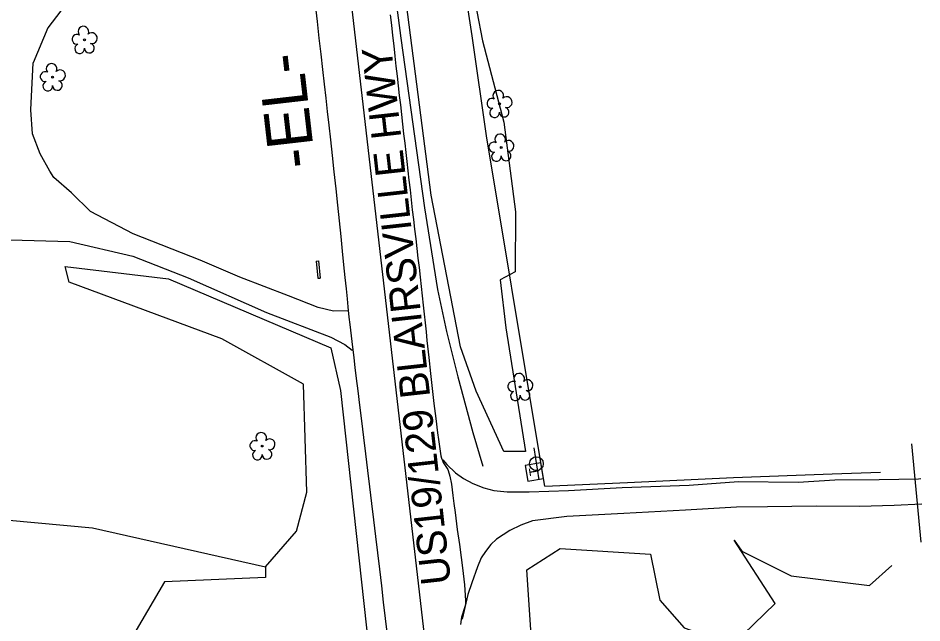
# Model space of a CAD drawing. Extents: x 476627 to 479509, y 495837 to 499842.
# Drawn here: x 478091.3 to 478407.5, y 496570.2 to 496781.9 of the extents above; entities that cross this region are included whole.
import ezdxf

# ---------------------------------------------------------------- set-up
doc = ezdxf.new("R2010")
doc.units = 0
for name, color, linetype in [('Exist Guardrail', 7, 'Continuous'), ('Exist Horizontal Alignment', 7, 'Continuous'), ('Exist Horizontal Alignment Direction Label', 7, 'Continuous'), ('Exist Other Culture Fence Line', 7, 'Continuous'), ('Exist Roads EOP', 7, 'Continuous'), ('Exist Roads EOP Other', 7, 'Continuous'), ('Exist Roads EOP Text', 7, 'Continuous'), ('Exist Roads Soil', 7, 'Continuous'), ('Exist Structure Minor Culvert Topo', 7, 'Continuous'), ('Exist Structure Minor Head and End Wall', 7, 'Continuous'), ('Exist Utilities Telephone Pedestal CELL', 7, 'Continuous'), ('Exist Utilities Telephone Pole CELL', 7, 'Continuous'), ('Exist Vegetation Hedge Row', 7, 'Continuous'), ('Exist Vegetation Tree CELL', 7, 'Continuous'), ('Exist Vegetation Woods Line', 7, 'Continuous')]:
    doc.layers.add(name, color=color, linetype=linetype)

msp = doc.modelspace()

# ---------------------------------------------------------------- linework, layer by layer
at = {"layer": 'Exist Guardrail'}
for points in [[(478213.59, 496874.62), (478218.27, 496827.31), (478225.22, 496774.85), (478233.42, 496715.49), (478237.99, 496686.86), (478241.19, 496672.25), (478245.14, 496656.32)], [(478245.14, 496656.32), (478250.34, 496636.91), (478253.8, 496625.04)]]:
    msp.add_lwpolyline(points, dxfattribs=at)
at = {"layer": 'Exist Horizontal Alignment'}
msp.add_line((478241.22, 496498.17), (478119.71, 497553.37), dxfattribs=at)
at = {"layer": 'Exist Other Culture Fence Line'}
msp.add_line((478275.55, 496618.08), (478267.31, 496667.66), dxfattribs=at)
for points in [[(478267.31, 496667.66), (478260.6, 496707.75), (478255.26, 496739.87), (478250.07, 496775.63), (478245.21, 496807.58), (478241.05, 496835.45)], [(478275.55, 496618.08), (478304.48, 496619.32), (478341.59, 496621.1), (478376.01, 496622.37), (478392.92, 496622.99)]]:
    msp.add_lwpolyline(points, dxfattribs=at)
at = {"layer": 'Exist Roads EOP'}
for points in [[(478220.46, 496566.1), (478219.81, 496571.81), (478219.16, 496577.52), (478218.5, 496583.26), (478217.83, 496589), (478217.14, 496594.76), (478216.45, 496600.52), (478215.76, 496606.29), (478215.05, 496612.05), (478214.35, 496617.82), (478213.64, 496623.58), (478212.93, 496629.35), (478212.21, 496635.13), (478211.49, 496640.91), (478210.81, 496646.42), (478210.2, 496651.38), (478209.66, 496655.79), (478209.2, 496659.64), (478208.79, 496663.04), (478208.1, 496668.69), (478207.39, 496674.6), (478207.11, 496677.26), (478206.76, 496680.8), (478206.48, 496683.6), (478206.12, 496687.09), (478205.7, 496691.11), (478205.25, 496695.51), (478204.77, 496700.29), (478204.24, 496705.45), (478203.69, 496710.88), (478203.11, 496716.45), (478202.51, 496722.17), (478201.89, 496728.05), (478201.27, 496733.83), (478200.68, 496739.27), (478200.11, 496744.37), (478199.57, 496749.14), (478199.04, 496753.84), (478198.47, 496758.76), (478197.88, 496763.89), (478197.27, 496769.24), (478196.63, 496774.81), (478195.99, 496780.62), (478195.34, 496786.66)], [(478221.49, 496783.04), (478221.9, 496779.4), (478222.3, 496775.76), (478222.7, 496772.14), (478223.09, 496768.55), (478223.48, 496765.03), (478223.86, 496761.57), (478224.24, 496758.18), (478224.62, 496754.82), (478225.01, 496751.46), (478225.39, 496748.1), (478225.78, 496744.73), (478226.16, 496741.39), (478226.53, 496738.09), (478226.9, 496734.84), (478227.26, 496731.62), (478227.62, 496728.4), (478228, 496725.1), (478228.38, 496721.72), (478228.77, 496718.28), (478229.17, 496714.81), (478229.57, 496711.38), (478229.97, 496707.97), (478230.37, 496704.6), (478230.77, 496701.24), (478231.17, 496697.89), (478231.56, 496694.55), (478231.95, 496691.22), (478232.33, 496687.92), (478232.69, 496684.67), (478233.03, 496681.46), (478233.36, 496678.31), (478233.68, 496675.2), (478233.99, 496672.12), (478234.3, 496669.08), (478234.91, 496663.14), (478235.53, 496657.52), (478236.15, 496652.22), (478236.77, 496646.98), (478237.39, 496641.78), (478238.02, 496636.79), (478238.34, 496634.39), (478239.2, 496628.72), (478239.43, 496627.85), (478239.69, 496627.07), (478240.01, 496626.37), (478241.4, 496624.24), (478241.56, 496623.93), (478241.7, 496623.6), (478242.34, 496621.54), (478242.86, 496618.75), (478243.39, 496614.84), (478243.76, 496611.96), (478244.16, 496608.83), (478244.93, 496602.97), (478245.64, 496597.66), (478246.25, 496593.16), (478246.74, 496589.45), (478247.42, 496583.58), (478247.81, 496578.07), (478247.74, 496576.9), (478247.56, 496575.82), (478246.43, 496572.21), (478246.26, 496571.37), (478246.08, 496569.68)]]:
    msp.add_lwpolyline(points, dxfattribs=at)
at = {"layer": 'Exist Roads EOP Other'}
for points in [[(478239.92, 496627.33), (478241.21, 496625.64), (478244.3, 496622.7), (478247.1, 496620.74), (478250.34, 496619), (478254.2, 496617.48), (478257.67, 496616.6), (478262.36, 496616.04), (478270.05, 496616.06), (478283.88, 496616.53), (478302.57, 496617.56), (478326, 496618.44), (478343.24, 496619.74), (478364.2, 496619.51), (478377.01, 496620.24), (478392.51, 496620.43), (478406.21, 496620.69), (478407.1, 496620.71)], [(478407.46, 496611.74), (478397.75, 496611.35), (478385.59, 496610.99), (478370.44, 496611.13), (478353.49, 496610.82), (478342.54, 496610.77), (478324.72, 496609.73), (478303.17, 496608.56), (478283.23, 496607.51), (478271.21, 496605.99), (478267.2, 496604.43), (478263.27, 496602.55), (478258.69, 496599.54), (478256.65, 496597.71), (478254.81, 496595.18), (478253.25, 496593.06), (478251.97, 496589.84), (478250.04, 496584.31), (478248.6, 496580.18), (478246.64, 496571.6)]]:
    msp.add_lwpolyline(points, dxfattribs=at)
at = {"layer": 'Exist Roads Soil'}
for points in [[(478189.67, 496831.06), (478186.75, 496829.54), (478180.04, 496831.02), (478171.59, 496834.23), (478168.6, 496834.12), (478165.53, 496833.64), (478158.26, 496830.84), (478147.06, 496822.45), (478128.57, 496805.81), (478111.16, 496790.92), (478101.72, 496778.39), (478096.6, 496766.23)], [(478206.6, 496679.48), (478201.62, 496679.26), (478196.25, 496680.56), (478185.83, 496684.68), (478168.81, 496691.15), (478154.93, 496697.17), (478131.53, 496706.42), (478116.63, 496714.23), (478109.99, 496720.71), (478103.79, 496726.07), (478102.44, 496728.29), (478099.03, 496734.39), (478096.35, 496741.32), (478095.7, 496749.77), (478096.6, 496766.23)], [(478086.69, 496742.93), (478086.87, 496725.81), (478088.51, 496704.3), (478109.37, 496703.66), (478131.43, 496698.61), (478150.79, 496691.03), (478178.23, 496678.82), (478200.68, 496670.27), (478205.54, 496667.62), (478208.17, 496665.62)]]:
    msp.add_lwpolyline(points, dxfattribs=at)
at = {"layer": 'Exist Structure Minor Culvert Topo'}
msp.add_line((478403.8, 496632.94), (478407.11, 496598.48), dxfattribs=at)
at = {"layer": 'Exist Structure Minor Head and End Wall'}
for p, q in [((478195.57, 496696.84), (478196.4, 496696.92)), ((478195.57, 496696.84), (478196.13, 496690.84)), ((478196.4, 496696.92), (478196.96, 496690.91)), ((478196.13, 496690.84), (478196.96, 496690.91))]:
    msp.add_line(p, q, dxfattribs=at)
at = {"layer": 'Exist Utilities Telephone Pedestal CELL'}
msp.add_line((478271.87, 496622.94), (478271.87, 496622.94), dxfattribs=at)
msp.add_lwpolyline([(478275.11, 496620.74), (478274.16, 496626.25), (478268.65, 496625.3), (478269.6, 496619.79), (478275.11, 496620.74)], dxfattribs=at)
at = {"layer": 'Exist Utilities Telephone Pole CELL'}
for p, q in [((478271.73, 496631.55), (478273.49, 496620.35)), ((478272.61, 496625.95), (478272.61, 496625.95))]:
    msp.add_line(p, q, dxfattribs=at)
msp.add_circle((478272.61, 496625.95), 2.41, dxfattribs=at)
at = {"layer": 'Exist Vegetation Hedge Row'}
for points in [[(478261.88, 496673.53), (478268.79, 496630.22), (478261.26, 496630.17), (478251.48, 496651.36), (478246, 496666.8), (478235.83, 496719.95), (478227.64, 496783.09), (478221.71, 496824.78), (478217.22, 496874.18), (478224.65, 496876.12), (478232.47, 496876.32), (478234.8, 496872.07), (478275.37, 496877.27), (478308.83, 496880.62), (478315.01, 496872.92), (478323.49, 496861.41), (478334.86, 496854.13), (478365.63, 496846.02)], [(478365.86, 496844.12), (478352.91, 496847.08), (478341.85, 496845.98), (478330.71, 496850.31), (478316.37, 496860.08), (478307.22, 496864.38), (478303.32, 496869.81), (478296.13, 496870.48), (478280.87, 496867.93), (478270.7, 496864.06), (478261.79, 496855.4), (478253.84, 496850.79), (478250.82, 496829.81), (478251.19, 496817), (478248.63, 496808.62), (478251.72, 496784.14), (478253.75, 496773.93), (478261.23, 496745.46), (478265.24, 496714.09), (478265.17, 496693.05), (478259.91, 496690.22)], [(478191.15, 496653.76), (478162.59, 496669.66), (478109.16, 496689.51), (478107.77, 496694.94), (478143.93, 496690.57), (478200.73, 496666.45), (478204.01, 496651.61)], [(478259.91, 496690.22), (478261.88, 496673.53)], [(478177.88, 496589.88), (478188.66, 496602.32), (478192.3, 496616.01), (478191.15, 496653.76)], [(478204.01, 496651.61), (478218.61, 496518.46), (478220.64, 496501.13)]]:
    msp.add_lwpolyline(points, dxfattribs=at)
at = {"layer": 'Exist Vegetation Tree CELL'}
for p, q in [((478114.51, 496774.24), (478114.51, 496774.24)), ((478103.37, 496761.21), (478103.37, 496761.21)), ((478259.66, 496751.85), (478259.66, 496751.85)), ((478260.31, 496736.55), (478260.31, 496736.55)), ((478266.95, 496652.8), (478266.95, 496652.8)), ((478176.7, 496632.12), (478176.7, 496632.12))]:
    msp.add_line(p, q, dxfattribs=at)
for centre in [(478114.51, 496774.24), (478103.37, 496761.21), (478259.66, 496751.85), (478260.31, 496736.55), (478266.95, 496652.8), (478176.7, 496632.12)]:
    msp.add_circle(centre, 0.326, dxfattribs=at)
for centre, radius, start, end in [((478114.13, 496777.12), 1.86, 330.1651, 219.7134), ((478111.91, 496774.4), 1.73, 62.6636, 279.3457), ((478117.06, 496774.83), 1.9, 257.1011, 134.1999), ((478112.81, 496771.12), 1.69, 111.5671, 6.231), ((478116.19, 496771.34), 1.7, 181.2822, 74.56), ((478102.99, 496764.08), 1.86, 330.1651, 219.7134), ((478100.76, 496761.36), 1.73, 62.6636, 279.3457), ((478105.92, 496761.8), 1.9, 257.1011, 134.1999), ((478101.67, 496758.09), 1.69, 111.5671, 6.231), ((478105.04, 496758.31), 1.7, 181.2822, 74.56), ((478259.27, 496754.72), 1.86, 330.1651, 219.7134), ((478257.05, 496752), 1.73, 62.6636, 279.3457), ((478262.21, 496752.44), 1.9, 257.1011, 134.1999), ((478257.95, 496748.73), 1.69, 111.5671, 6.231), ((478261.33, 496748.95), 1.7, 181.2822, 74.56), ((478259.92, 496739.42), 1.86, 330.1651, 219.7134), ((478257.7, 496736.7), 1.73, 62.6636, 279.3457), ((478262.85, 496737.14), 1.9, 257.1011, 134.1999), ((478258.6, 496733.43), 1.69, 111.5671, 6.231), ((478261.98, 496733.65), 1.7, 181.2822, 74.56), ((478266.56, 496655.68), 1.86, 330.1651, 219.7134), ((478264.34, 496652.96), 1.73, 62.6636, 279.3457), ((478269.5, 496653.39), 1.9, 257.1011, 134.1999), ((478265.24, 496649.68), 1.69, 111.5671, 6.231), ((478268.62, 496649.9), 1.7, 181.2822, 74.56), ((478176.32, 496634.99), 1.86, 330.1651, 219.7134), ((478174.1, 496632.27), 1.73, 62.6636, 279.3457), ((478179.25, 496632.71), 1.9, 257.1011, 134.1999), ((478175, 496629), 1.69, 111.5671, 6.231), ((478178.38, 496629.22), 1.7, 181.2822, 74.56)]:
    msp.add_arc(centre, radius, start, end, dxfattribs=at)
at = {"layer": 'Exist Vegetation Woods Line'}
for points in [[(478067.75, 496608.04), (478117.36, 496603.45), (478177.88, 496589.88), (478177.8, 496586.07), (478142.44, 496584.63), (478109.62, 496528.51), (478093.53, 496512.14), (478082.21, 496482.6)], [(478275.03, 496501.06), (478269.24, 496588.78), (478280.93, 496596.29), (478312.46, 496594.29), (478315.77, 496578.25), (478324.29, 496568.51), (478341.22, 496562.61), (478356.13, 496577.03), (478341.76, 496599.15), (478344.52, 496595.39), (478361.67, 496586.74), (478389.14, 496583.27), (478396.92, 496590.28)]]:
    msp.add_lwpolyline(points, dxfattribs=at)

# ---------------------------------------------------------------- texts
at = {"layer": 'Exist Horizontal Alignment Direction Label'}
msp.add_text('-EL-', height=16, rotation=96.5685, dxfattribs=at).set_placement((478195.36, 496730.08))
at = {"layer": 'Exist Roads EOP Text'}
msp.add_text('US19/129 BLAIRSVILLE HWY', height=10.4, rotation=96.3583, dxfattribs=at).set_placement((478242.76, 496584.08))
at = {"layer": 'Exist Utilities Telephone Pedestal CELL'}
msp.add_text('T', height=3.42, rotation=99.7763, dxfattribs=at).set_placement((478273.75, 496622.12))

doc.saveas('drawing.dxf')
